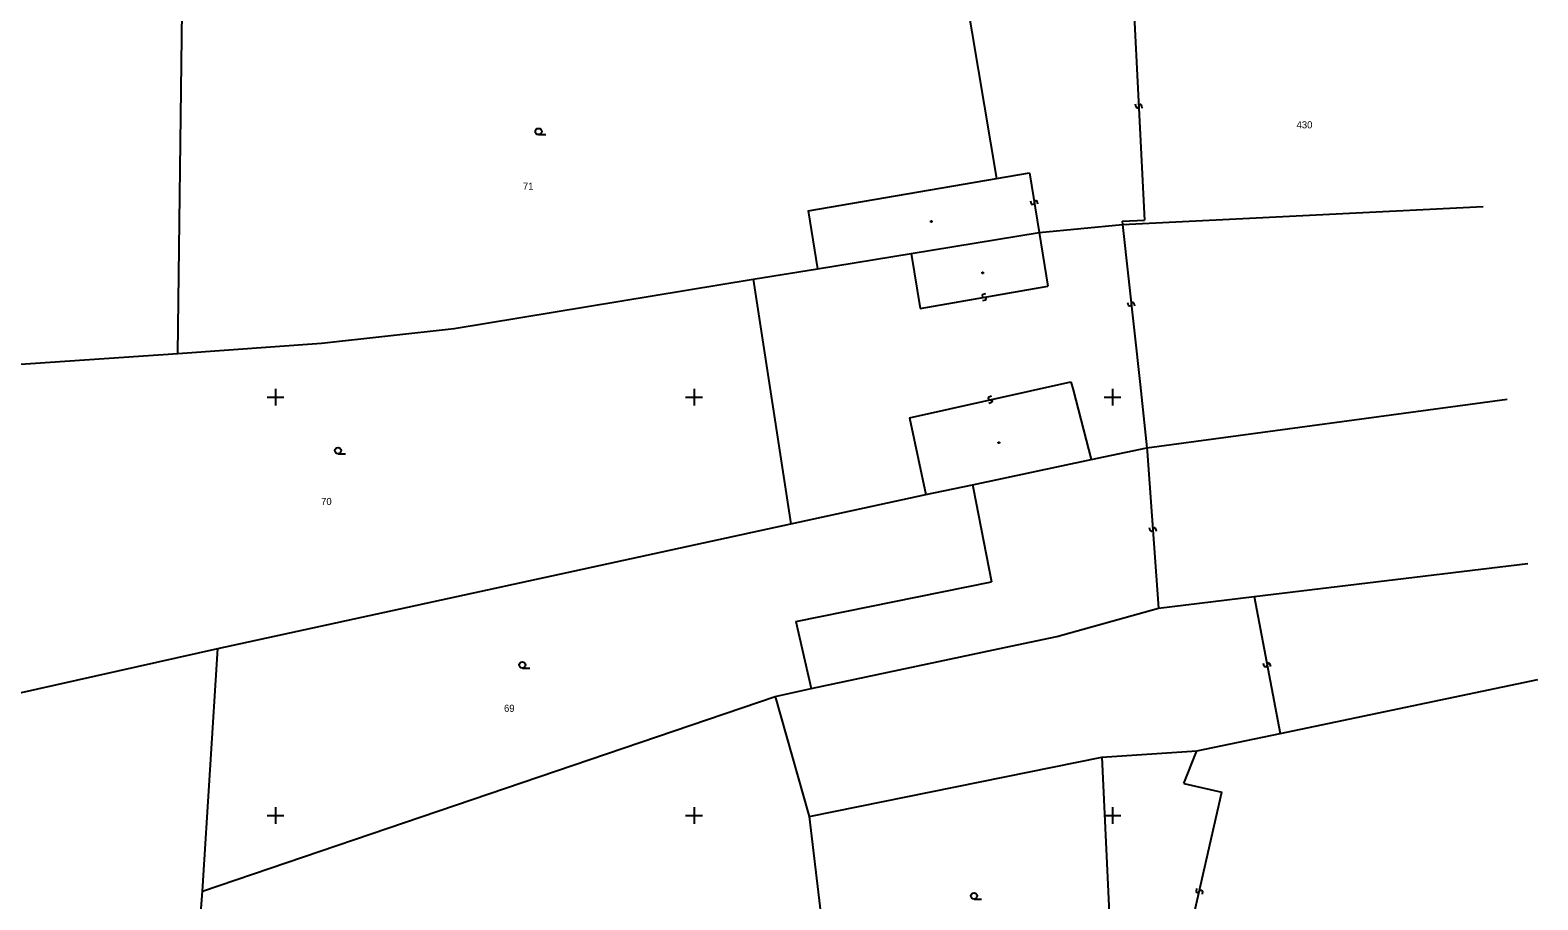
# Model space of a CAD drawing. Extents: x -492811 to -492366, y -1127107 to -1126748.
# Drawn here: x -492491.7 to -492419.7, y -1126844 to -1126802.4 of the extents above; entities that cross this region are included whole.
import ezdxf

# ---------------------------------------------------------------- set-up
doc = ezdxf.new("R2010")
doc.units = 0
doc.layers.add('katastrální mapa', color=7, linetype='Continuous')
doc.layers.add('síť', color=7, linetype='Continuous')

msp = doc.modelspace()

# ---------------------------------------------------------------- linework, layer by layer
at = {"layer": 'katastrální mapa'}
for p, q in [((-492447.02, -1126800.81), (-492445.55, -1126809.54)), ((-492439.02, -1126800.64), (-492438.47, -1126811.53)), ((-492484.66, -1126817.9), (-492484.46, -1126801.52)), ((-492438.88, -1126806.13), (-492438.91, -1126805.99)), ((-492438.69, -1126806), (-492438.73, -1126806.04)), ((-492438.65, -1126806), (-492438.69, -1126806)), ((-492438.61, -1126806.04), (-492438.65, -1126806)), ((-492438.84, -1126806.17), (-492438.88, -1126806.13)), ((-492438.8, -1126806.17), (-492438.84, -1126806.17)), ((-492438.76, -1126806.13), (-492438.8, -1126806.17)), ((-492438.73, -1126806.04), (-492438.76, -1126806.13)), ((-492438.58, -1126806.18), (-492438.61, -1126806.04)), ((-492467.43, -1126807.44), (-492467.08, -1126807.44)), ((-492454.55, -1126811.09), (-492445.55, -1126809.54)), ((-492445.55, -1126809.54), (-492443.97, -1126809.27)), ((-492443.97, -1126809.27), (-492443.51, -1126812.12)), ((-492443.87, -1126810.76), (-492443.91, -1126810.62)), ((-492443.83, -1126810.79), (-492443.87, -1126810.76)), ((-492443.79, -1126810.78), (-492443.83, -1126810.79)), ((-492443.75, -1126810.74), (-492443.79, -1126810.78)), ((-492443.73, -1126810.65), (-492443.75, -1126810.74)), ((-492443.69, -1126810.61), (-492443.73, -1126810.65)), ((-492443.65, -1126810.6), (-492443.69, -1126810.61)), ((-492443.61, -1126810.63), (-492443.65, -1126810.6)), ((-492443.57, -1126810.77), (-492443.61, -1126810.63)), ((-492439.52, -1126811.73), (-492422.3, -1126810.88)), ((-492454.55, -1126811.09), (-492454.1, -1126813.85)), ((-492448.69, -1126811.57), (-492448.63, -1126811.57)), ((-492448.69, -1126811.63), (-492448.69, -1126811.57)), ((-492448.63, -1126811.63), (-492448.69, -1126811.63)), ((-492448.63, -1126811.57), (-492448.63, -1126811.63)), ((-492443.51, -1126812.12), (-492439.52, -1126811.73)), ((-492439.54, -1126811.58), (-492438.47, -1126811.53)), ((-492439.54, -1126811.58), (-492439.52, -1126811.73)), ((-492439.52, -1126811.73), (-492438.69, -1126819.39)), ((-492449.62, -1126813.12), (-492443.51, -1126812.12)), ((-492443.51, -1126812.12), (-492443.09, -1126814.68)), ((-492454.1, -1126813.85), (-492449.62, -1126813.12)), ((-492449.62, -1126813.12), (-492449.19, -1126815.76)), ((-492457.18, -1126814.35), (-492454.1, -1126813.85)), ((-492471.46, -1126816.71), (-492457.18, -1126814.35)), ((-492457.18, -1126814.35), (-492455.37, -1126826.05)), ((-492446.24, -1126814.02), (-492446.18, -1126814.02)), ((-492446.24, -1126814.08), (-492446.24, -1126814.02)), ((-492446.18, -1126814.08), (-492446.24, -1126814.08)), ((-492446.18, -1126814.02), (-492446.18, -1126814.08)), ((-492449.19, -1126815.76), (-492443.09, -1126814.68)), ((-492446.2, -1126815.09), (-492446.24, -1126815.14)), ((-492446.24, -1126815.14), (-492446.23, -1126815.17)), ((-492446.23, -1126815.17), (-492446.18, -1126815.21)), ((-492446.08, -1126815.35), (-492446.21, -1126815.39)), ((-492446.07, -1126815.05), (-492446.2, -1126815.09)), ((-492446.18, -1126815.21), (-492446.1, -1126815.23)), ((-492446.1, -1126815.23), (-492446.05, -1126815.27)), ((-492446.04, -1126815.3), (-492446.08, -1126815.35)), ((-492446.05, -1126815.27), (-492446.04, -1126815.3)), ((-492439.24, -1126815.61), (-492439.27, -1126815.48)), ((-492439.2, -1126815.65), (-492439.24, -1126815.61)), ((-492439.16, -1126815.65), (-492439.2, -1126815.65)), ((-492439.12, -1126815.6), (-492439.16, -1126815.65)), ((-492439.09, -1126815.52), (-492439.12, -1126815.6)), ((-492439.05, -1126815.47), (-492439.09, -1126815.52)), ((-492439.01, -1126815.47), (-492439.05, -1126815.47)), ((-492438.97, -1126815.51), (-492439.01, -1126815.47)), ((-492438.94, -1126815.64), (-492438.97, -1126815.51)), ((-492477.8, -1126817.41), (-492471.46, -1126816.71)), ((-492484.66, -1126817.9), (-492477.8, -1126817.41)), ((-492494.47, -1126818.57), (-492484.66, -1126817.9)), ((-492449.7, -1126820.98), (-492441.99, -1126819.26)), ((-492441.99, -1126819.26), (-492441.89, -1126819.64)), ((-492441.89, -1126819.64), (-492441.03, -1126822.98)), ((-492438.69, -1126819.39), (-492438.36, -1126822.42)), ((-492445.91, -1126819.99), (-492445.94, -1126820.04)), ((-492445.94, -1126820.04), (-492445.94, -1126820.08)), ((-492445.94, -1126820.08), (-492445.89, -1126820.11)), ((-492445.78, -1126819.94), (-492445.91, -1126819.99)), ((-492445.78, -1126820.25), (-492445.91, -1126820.3)), ((-492445.89, -1126820.11), (-492445.8, -1126820.13)), ((-492445.8, -1126820.13), (-492445.75, -1126820.16)), ((-492445.75, -1126820.2), (-492445.78, -1126820.25)), ((-492445.75, -1126820.16), (-492445.75, -1126820.2)), ((-492438.36, -1126822.42), (-492421.14, -1126820.09)), ((-492449.7, -1126820.98), (-492448.92, -1126824.65)), ((-492445.46, -1126822.14), (-492445.4, -1126822.14)), ((-492445.46, -1126822.2), (-492445.46, -1126822.14)), ((-492445.4, -1126822.2), (-492445.46, -1126822.2)), ((-492445.4, -1126822.14), (-492445.4, -1126822.2)), ((-492441.03, -1126822.98), (-492438.36, -1126822.42)), ((-492438.36, -1126822.42), (-492438.34, -1126822.57)), ((-492438.34, -1126822.57), (-492437.8, -1126830.08)), ((-492477.01, -1126822.7), (-492476.66, -1126822.7)), ((-492446.69, -1126824.18), (-492441.03, -1126822.98)), ((-492455.37, -1126826.05), (-492448.92, -1126824.65)), ((-492448.92, -1126824.65), (-492446.69, -1126824.18)), ((-492446.69, -1126824.18), (-492446.66, -1126824.33)), ((-492446.66, -1126824.33), (-492445.78, -1126828.82)), ((-492482.75, -1126832.01), (-492455.37, -1126826.05)), ((-492438.21, -1126826.37), (-492438.24, -1126826.24)), ((-492438.16, -1126826.41), (-492438.21, -1126826.37)), ((-492438.12, -1126826.41), (-492438.16, -1126826.41)), ((-492438.09, -1126826.37), (-492438.12, -1126826.41)), ((-492438.05, -1126826.28), (-492438.09, -1126826.37)), ((-492438.02, -1126826.24), (-492438.05, -1126826.28)), ((-492437.98, -1126826.24), (-492438.02, -1126826.24)), ((-492437.93, -1126826.28), (-492437.98, -1126826.24)), ((-492437.9, -1126826.41), (-492437.93, -1126826.28)), ((-492433.23, -1126829.53), (-492420.16, -1126827.94)), ((-492455.13, -1126830.72), (-492445.78, -1126828.82)), ((-492437.8, -1126830.08), (-492433.23, -1126829.53)), ((-492433.23, -1126829.53), (-492432, -1126836.07)), ((-492442.67, -1126831.43), (-492437.8, -1126830.08)), ((-492455.13, -1126830.72), (-492454.4, -1126833.93)), ((-492445.16, -1126831.96), (-492442.67, -1126831.43)), ((-492493.46, -1126834.41), (-492482.75, -1126832.01)), ((-492483.49, -1126843.61), (-492482.75, -1126832.01)), ((-492454.4, -1126833.93), (-492445.16, -1126831.96)), ((-492468.2, -1126832.95), (-492467.85, -1126832.95)), ((-492432.75, -1126832.87), (-492432.79, -1126832.73)), ((-492432.7, -1126832.9), (-492432.75, -1126832.87)), ((-492432.66, -1126832.89), (-492432.7, -1126832.9)), ((-492432.63, -1126832.84), (-492432.66, -1126832.89)), ((-492432.6, -1126832.76), (-492432.63, -1126832.84)), ((-492432.57, -1126832.71), (-492432.6, -1126832.76)), ((-492432.53, -1126832.7), (-492432.57, -1126832.71)), ((-492432.48, -1126832.73), (-492432.53, -1126832.7)), ((-492432.44, -1126832.87), (-492432.48, -1126832.73)), ((-492456.12, -1126834.3), (-492454.4, -1126833.93)), ((-492432, -1126836.07), (-492419.68, -1126833.5)), ((-492483.49, -1126843.61), (-492456.12, -1126834.3)), ((-492456.12, -1126834.3), (-492454.5, -1126840.05)), ((-492435.98, -1126836.91), (-492432, -1126836.07)), ((-492440.52, -1126837.21), (-492435.98, -1126836.91)), ((-492436.59, -1126838.47), (-492435.98, -1126836.91)), ((-492454.5, -1126840.05), (-492440.52, -1126837.21)), ((-492440.52, -1126837.21), (-492439.96, -1126849.01)), ((-492436.93, -1126848.36), (-492434.78, -1126838.88)), ((-492436.59, -1126838.47), (-492434.78, -1126838.88)), ((-492454.5, -1126840.05), (-492453.76, -1126846.29)), ((-492483.79, -1126847.63), (-492483.49, -1126843.61)), ((-492446.62, -1126843.99), (-492446.27, -1126843.99)), ((-492435.99, -1126843.49), (-492436, -1126843.63)), ((-492436, -1126843.63), (-492435.97, -1126843.68)), ((-492435.97, -1126843.68), (-492435.93, -1126843.68)), ((-492435.93, -1126843.68), (-492435.88, -1126843.65)), ((-492435.88, -1126843.65), (-492435.83, -1126843.59)), ((-492435.83, -1126843.59), (-492435.78, -1126843.56)), ((-492435.78, -1126843.56), (-492435.74, -1126843.56)), ((-492435.74, -1126843.56), (-492435.71, -1126843.61)), ((-492435.71, -1126843.61), (-492435.72, -1126843.75))]:
    msp.add_line(p, q, dxfattribs=at)
for centre in [(-492467.43, -1126807.29), (-492477.01, -1126822.55), (-492468.2, -1126832.8), (-492446.62, -1126843.84)]:
    msp.add_circle(centre, 0.15, dxfattribs=at)
at = {"layer": 'síť'}
for p, q in [((-492480, -1126819.6), (-492480, -1126820.4)), ((-492460, -1126819.6), (-492460, -1126820.4)), ((-492440, -1126819.6), (-492440, -1126820.4)), ((-492480.4, -1126820), (-492479.6, -1126820)), ((-492460.4, -1126820), (-492459.6, -1126820)), ((-492440.4, -1126820), (-492439.6, -1126820)), ((-492480, -1126839.6), (-492480, -1126840.4)), ((-492460, -1126839.6), (-492460, -1126840.4)), ((-492440, -1126839.6), (-492440, -1126840.4)), ((-492480.4, -1126840), (-492479.6, -1126840)), ((-492460.4, -1126840), (-492459.6, -1126840)), ((-492440.4, -1126840), (-492439.6, -1126840))]:
    msp.add_line(p, q, dxfattribs=at)

# ---------------------------------------------------------------- texts
at = {"layer": 'katastrální mapa'}
for s, p in [('430', (-492431.21, -1126807.14)), ('71', (-492468.18, -1126810.08)), ('70', (-492477.82, -1126825.15)), ('69', (-492469.08, -1126835.04))]:
    msp.add_text(s, height=0.34, dxfattribs=at).set_placement(p)

doc.saveas('drawing.dxf')
